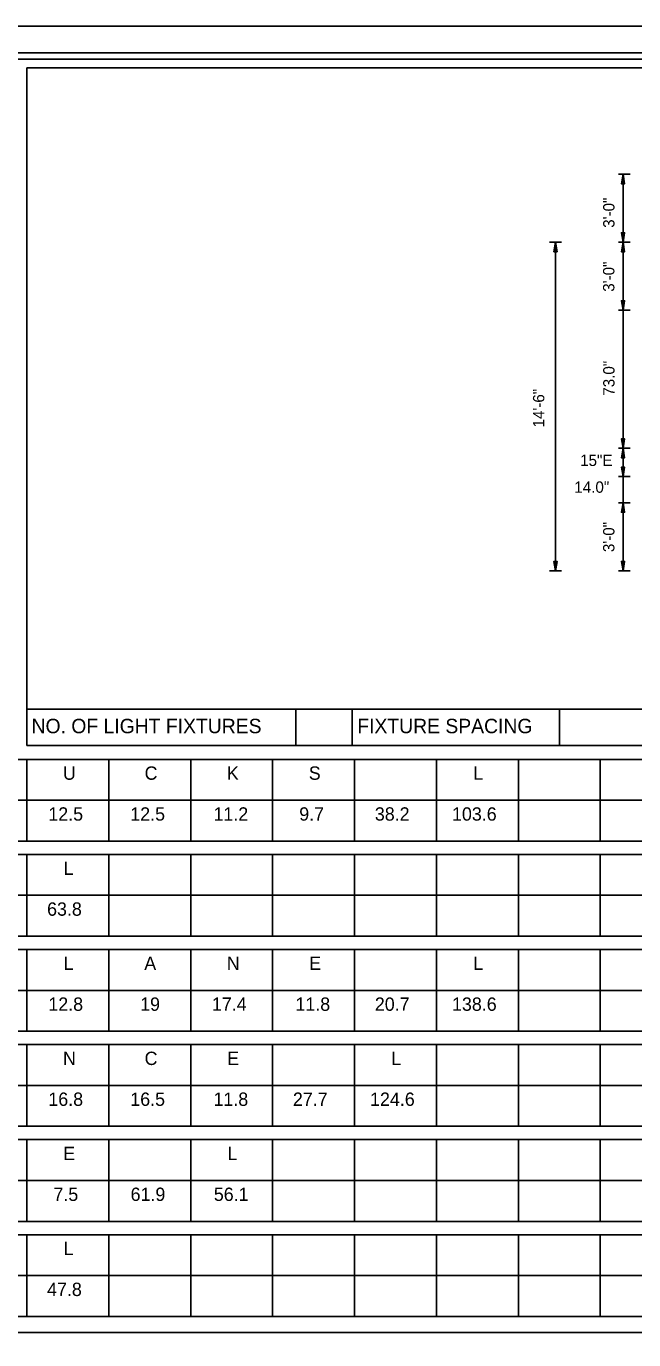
# Model space of a CAD drawing. Extents: x 119523 to 121850, y -23542 to -19972.
# Drawn here: x 119943 to 120264, y -22723 to -22028 of the extents above; entities that cross this region are included whole.
import ezdxf

# ---------------------------------------------------------------- set-up
doc = ezdxf.new("R2010")
doc.units = 0
for name, color, linetype in [('GSDims', 7, 'Continuous'), ('PlotBorder_dp', 7, 'Continuous'), ('SheetBorder_dp', 7, 'Continuous'), ('SheetLinesMisc2_dp', 7, 'Continuous'), ('TextMinor', 7, 'Continuous')]:
    doc.layers.add(name, color=color, linetype=linetype)

msp = doc.modelspace()

# ---------------------------------------------------------------- linework, layer by layer
at = {"layer": 'GSDims'}
for p, q in [((120262.52, -22106.11), (120256.27, -22106.11)), ((120258.77, -22142.11), (120258.77, -22106.11)), ((120262.52, -22106.11), (120262.52, -22106.11)), ((120226.15, -22142.11), (120219.9, -22142.11)), ((120223.03, -22316.11), (120223.03, -22142.11)), ((120262.52, -22142.11), (120256.27, -22142.11)), ((120262.52, -22142.11), (120256.27, -22142.11)), ((120258.77, -22251.21), (120258.77, -22142.11)), ((120262.52, -22142.11), (120262.52, -22142.11)), ((120262.52, -22178.11), (120256.27, -22178.11)), ((120262.52, -22251.21), (120256.27, -22251.21)), ((120262.52, -22251.21), (120256.27, -22251.21)), ((120258.77, -22251.21), (120258.77, -22266.21)), ((120262.52, -22266.21), (120256.27, -22266.21)), ((120262.52, -22266.21), (120256.27, -22266.21)), ((120258.77, -22316.11), (120258.77, -22266.21)), ((120262.52, -22280.1), (120256.27, -22280.1)), ((120226.15, -22316.11), (120219.9, -22316.11)), ((120262.52, -22316.11), (120256.27, -22316.11)), ((120262.52, -22316.11), (120256.27, -22316.11))]:
    msp.add_line(p, q, dxfattribs=at)
for points in [[(120258.77, -22106.11), (120259.61, -22111.11), (120257.94, -22111.11)], [(120258.77, -22142.11), (120259.61, -22137.11), (120257.94, -22137.11)], [(120223.03, -22142.11), (120223.86, -22147.11), (120222.2, -22147.11)], [(120258.77, -22142.11), (120259.61, -22147.11), (120257.94, -22147.11)], [(120258.77, -22178.11), (120259.61, -22173.11), (120257.94, -22173.11)], [(120258.77, -22251.21), (120259.61, -22246.21), (120257.94, -22246.21)], [(120258.77, -22251.21), (120259.61, -22256.21), (120257.94, -22256.21)], [(120258.77, -22266.21), (120259.61, -22261.21), (120257.94, -22261.21)], [(120258.77, -22280.1), (120259.61, -22285.1), (120257.94, -22285.1)], [(120223.03, -22316.11), (120223.86, -22311.11), (120222.2, -22311.11)], [(120258.77, -22316.11), (120259.61, -22311.11), (120257.94, -22311.11)]]:
    msp.add_lwpolyline(points, close=True, dxfattribs=at)
at = {"layer": 'PlotBorder_dp'}
msp.add_lwpolyline([(119522.87, -23522.86), (121850.2, -23522.86), (121850.2, -22027.72), (119522.87, -22027.72)], close=True, dxfattribs=at)
at = {"layer": 'SheetBorder_dp'}
msp.add_line((119600.45, -22041.83), (121772.62, -22041.83), dxfattribs=at)
at = {"layer": 'SheetLinesMisc2_dp'}
for p, q in [((119604.34, -22045.17), (121770.65, -22045.17)), ((119943.36, -22049.66), (120680.14, -22049.66)), ((119943.36, -22049.66), (119943.36, -22408.55)), ((119943.36, -22389.32), (120680.14, -22389.32)), ((120085.67, -22389.32), (120085.67, -22408.55)), ((120115.49, -22389.32), (120115.49, -22408.55)), ((120225.2, -22389.32), (120225.2, -22408.55)), ((119943.36, -22408.55), (120680.14, -22408.55)), ((119614.73, -22415.94), (120680.14, -22415.94)), ((119943.36, -22415.94), (119943.36, -22459.23)), ((119986.7, -22415.94), (119986.7, -22459.23)), ((120030.03, -22415.94), (120030.03, -22459.23)), ((120073.37, -22415.94), (120073.37, -22459.23)), ((120116.72, -22415.94), (120116.72, -22459.23)), ((120160.06, -22415.94), (120160.06, -22459.23)), ((120203.39, -22415.94), (120203.39, -22459.23)), ((120246.73, -22415.94), (120246.73, -22459.23)), ((119614.73, -22437.58), (120680.14, -22437.58)), ((119614.73, -22459.23), (120680.14, -22459.23)), ((119614.73, -22466.29), (120680.14, -22466.29)), ((119943.36, -22466.29), (119943.36, -22509.57)), ((119986.7, -22466.29), (119986.7, -22509.57)), ((120030.03, -22466.29), (120030.03, -22509.57)), ((120073.37, -22466.29), (120073.37, -22509.57)), ((120116.72, -22466.29), (120116.72, -22509.57)), ((120160.06, -22466.29), (120160.06, -22509.57)), ((120203.39, -22466.29), (120203.39, -22509.57)), ((120246.73, -22466.29), (120246.73, -22509.57)), ((119614.73, -22487.94), (120680.14, -22487.92)), ((119614.73, -22509.57), (120680.14, -22509.57)), ((119614.73, -22516.62), (120680.14, -22516.62)), ((119943.36, -22516.62), (119943.36, -22559.91)), ((119986.7, -22516.62), (119986.7, -22559.91)), ((120030.03, -22516.62), (120030.03, -22559.91)), ((120073.37, -22516.62), (120073.37, -22559.91)), ((120116.72, -22516.62), (120116.72, -22559.91)), ((120160.06, -22516.62), (120160.06, -22559.91)), ((120203.39, -22516.62), (120203.39, -22559.91)), ((120246.73, -22516.62), (120246.73, -22559.91)), ((119614.73, -22538.27), (120680.14, -22538.27)), ((119614.73, -22559.91), (120680.14, -22559.91)), ((119614.73, -22566.96), (120680.14, -22566.96)), ((119943.36, -22566.96), (119943.36, -22610.25)), ((119986.7, -22566.96), (119986.7, -22610.25)), ((120030.03, -22566.96), (120030.03, -22610.25)), ((120073.37, -22566.96), (120073.37, -22610.25)), ((120116.72, -22566.96), (120116.72, -22610.25)), ((120160.06, -22566.96), (120160.06, -22610.25)), ((120203.39, -22566.96), (120203.39, -22610.25)), ((120246.73, -22566.96), (120246.73, -22610.25)), ((119614.73, -22588.61), (120680.14, -22588.61)), ((119614.73, -22610.25), (120680.14, -22610.25)), ((119614.73, -22617.31), (120680.14, -22617.31)), ((119943.36, -22617.31), (119943.36, -22660.59)), ((119986.7, -22617.31), (119986.7, -22660.59)), ((120030.03, -22617.31), (120030.03, -22660.59)), ((120073.37, -22617.31), (120073.37, -22660.59)), ((120116.72, -22617.31), (120116.72, -22660.59)), ((120160.06, -22617.31), (120160.06, -22660.59)), ((120203.39, -22617.31), (120203.39, -22660.59)), ((120246.73, -22617.31), (120246.73, -22660.59)), ((119614.73, -22638.95), (120680.14, -22638.95)), ((119614.73, -22660.59), (120680.14, -22660.59)), ((119614.73, -22667.65), (120680.14, -22667.65)), ((119943.36, -22667.65), (119943.36, -22710.93)), ((119986.7, -22667.65), (119986.7, -22710.93)), ((120030.03, -22667.65), (120030.03, -22710.93)), ((120073.37, -22667.65), (120073.37, -22710.93)), ((120116.72, -22667.65), (120116.72, -22710.93)), ((120160.06, -22667.65), (120160.06, -22710.93)), ((120203.39, -22667.65), (120203.39, -22710.93)), ((120246.73, -22667.65), (120246.73, -22710.93)), ((119614.73, -22689.28), (120680.14, -22689.28)), ((119614.73, -22710.93), (120680.14, -22710.93)), ((119604.34, -22719.43), (121770.65, -22719.43))]:
    msp.add_line(p, q, dxfattribs=at)

# ---------------------------------------------------------------- texts
at = {"layer": 'GSDims'}
for s, rotation, p in [('3\'-0"', 90, (120254.24, -22134.45)), ('3\'-0"', 90, (120254.18, -22168.31)), ('73.0"', 90, (120254.25, -22223.35)), ('14\'-6"', 90, (120217.12, -22240.18)), ('15"E', 360, (120236.06, -22260.57)), ('14.0"', 360, (120232.99, -22274.75)), ('3\'-0"', 90, (120254.2, -22306.18))]:
    msp.add_text(s, height=6, rotation=rotation, dxfattribs=at).set_placement(p)
for s, height, p in [('U', 7.06, (119962.45, -22426.76)), ('C', 7.06, (120005.64, -22426.76)), ('K', 7.06, (120049.15, -22426.76)), ('S', 7.06, (120092.5, -22426.76)), ('L', 7.06, (120179.54, -22426.76)), ('12.5', 7.058, (119954.72, -22448.4)), ('12.5', 7.058, (119998.07, -22448.4)), ('11.2', 7.058, (120042.09, -22448.4)), ('9.7', 7.058, (120087.46, -22448.4)), ('38.2', 7.058, (120127.45, -22448.4)), ('103.6', 7.058, (120168.28, -22448.4)), ('L', 7.06, (119962.79, -22477.11)), ('63.8', 7.058, (119954.05, -22498.75)), ('L', 7.06, (119962.79, -22527.46)), ('A', 7.06, (120005.47, -22527.46)), ('N', 7.06, (120049.15, -22527.46)), ('E', 7.06, (120092.67, -22527.46)), ('L', 7.06, (120179.54, -22527.46)), ('12.8', 7.058, (119954.72, -22549.1)), ('19', 7.058, (120003.28, -22549.1)), ('17.4', 7.058, (120041.25, -22549.1)), ('11.8', 7.058, (120085.44, -22549.1)), ('20.7', 7.058, (120127.45, -22549.1)), ('138.6', 7.058, (120168.28, -22549.1)), ('N', 7.06, (119962.45, -22577.8)), ('C', 7.06, (120005.64, -22577.8)), ('E', 7.06, (120049.32, -22577.8)), ('L', 7.06, (120136.19, -22577.8)), ('16.8', 7.058, (119954.72, -22599.44)), ('16.5', 7.058, (119998.07, -22599.44)), ('11.8', 7.058, (120042.09, -22599.44)), ('27.7', 7.058, (120084.1, -22599.44)), ('124.6', 7.058, (120124.93, -22599.44)), ('E', 7.06, (119962.62, -22628.15)), ('L', 7.06, (120049.49, -22628.15)), ('7.5', 7.058, (119957.41, -22649.79)), ('61.9', 7.058, (119998.24, -22649.79)), ('56.1', 7.058, (120042.26, -22649.79)), ('L', 7.06, (119962.79, -22678.49)), ('47.8', 7.058, (119954.05, -22700.14))]:
    msp.add_text(s, height=height, dxfattribs=at).set_placement(p)
at = {"layer": 'TextMinor'}
for s, p in [('NO. OF LIGHT FIXTURES', (119945.83, -22402.11)), ('FIXTURE SPACING', (120118.14, -22402.11))]:
    msp.add_text(s, height=7.6529, dxfattribs=at).set_placement(p)

doc.saveas('drawing.dxf')
